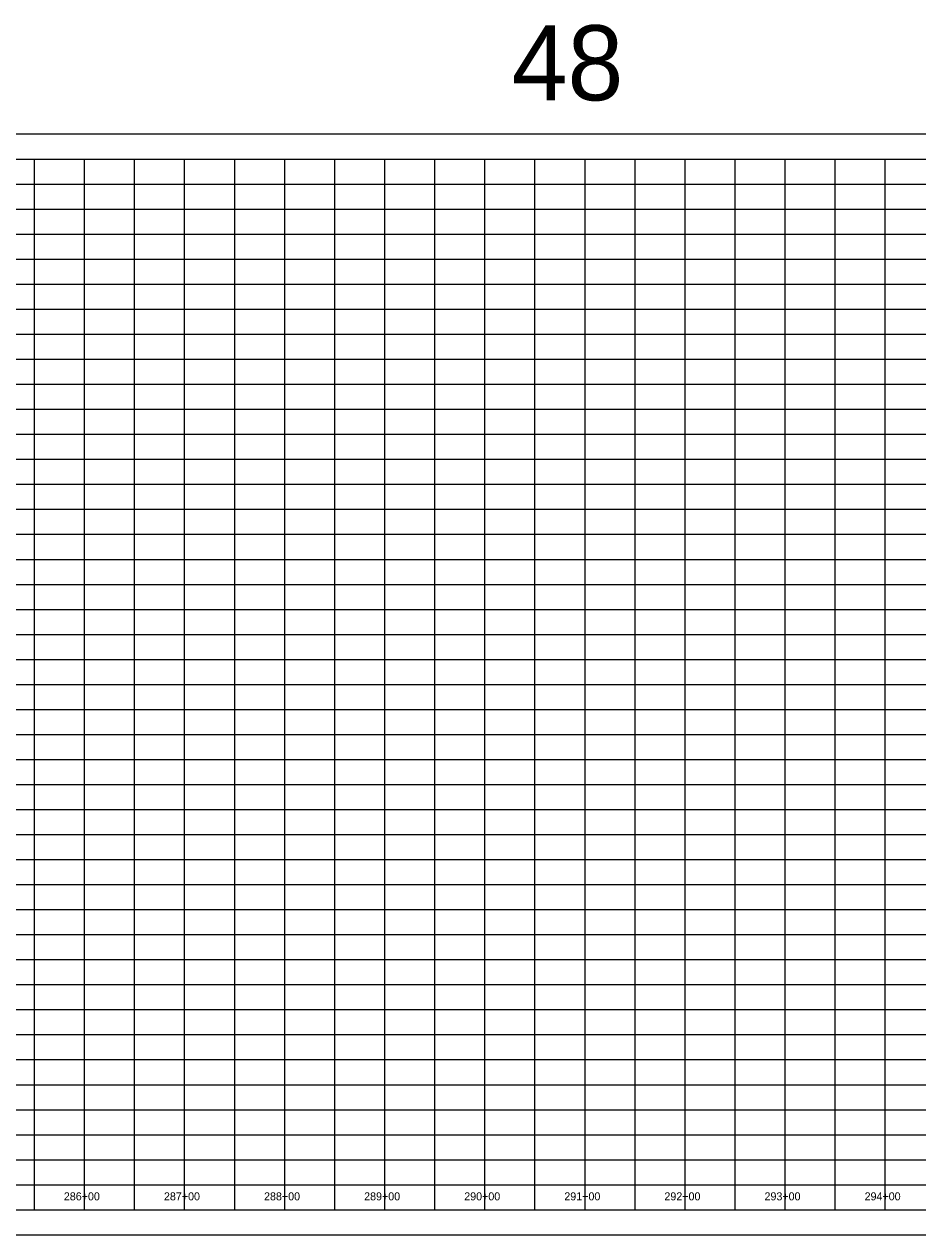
# Model space of a CAD drawing. Extents: x 1873632 to 1926512, y 813126 to 836257.
# Drawn here: x 1906903 to 1907795, y 827963 to 829173 of the extents above; entities that cross this region are included whole.
import ezdxf

# ---------------------------------------------------------------- set-up
doc = ezdxf.new("R2010")
doc.units = 0
for name, color, linetype in [('RD_DDB_StaTX', 7, 'Continuous'), ('RD_PD_WallFill', 7, 'Continuous'), ('RD_SHT_IplotShp', 7, 'Continuous')]:
    doc.layers.add(name, color=color, linetype=linetype)

msp = doc.modelspace()

# ---------------------------------------------------------------- linework, layer by layer
at = {"layer": 'RD_PD_WallFill'}
for p, q in [((1905062.9, 829038.1), (1910412.9, 829038.1)), ((1906912.9, 827988.1), (1906912.9, 829038.1)), ((1906912.9, 827988.1), (1906912.9, 829038.1)), ((1906962.9, 827988.1), (1906962.9, 829038.1)), ((1906962.9, 827988.1), (1906962.9, 829038.1)), ((1907012.9, 827988.1), (1907012.9, 829038.1)), ((1907012.9, 827988.1), (1907012.9, 829038.1)), ((1907062.9, 827988.1), (1907062.9, 829038.1)), ((1907062.9, 827988.1), (1907062.9, 829038.1)), ((1907112.9, 827988.1), (1907112.9, 829038.1)), ((1907112.9, 827988.1), (1907112.9, 829038.1)), ((1907162.9, 827988.1), (1907162.9, 829038.1)), ((1907162.9, 827988.1), (1907162.9, 829038.1)), ((1907212.9, 827988.1), (1907212.9, 829038.1)), ((1907212.9, 827988.1), (1907212.9, 829038.1)), ((1907262.9, 827988.1), (1907262.9, 829038.1)), ((1907262.9, 827988.1), (1907262.9, 829038.1)), ((1907312.9, 827988.1), (1907312.9, 829038.1)), ((1907312.9, 827988.1), (1907312.9, 829038.1)), ((1907362.9, 827988.1), (1907362.9, 829038.1)), ((1907362.9, 827988.1), (1907362.9, 829038.1)), ((1907412.9, 827988.1), (1907412.9, 829038.1)), ((1907412.9, 827988.1), (1907412.9, 829038.1)), ((1907462.9, 827988.1), (1907462.9, 829038.1)), ((1907462.9, 827988.1), (1907462.9, 829038.1)), ((1907512.9, 827988.1), (1907512.9, 829038.1)), ((1907512.9, 827988.1), (1907512.9, 829038.1)), ((1907562.9, 827988.1), (1907562.9, 829038.1)), ((1907562.9, 827988.1), (1907562.9, 829038.1)), ((1907612.9, 827988.1), (1907612.9, 829038.1)), ((1907612.9, 827988.1), (1907612.9, 829038.1)), ((1907662.9, 827988.1), (1907662.9, 829038.1)), ((1907662.9, 827988.1), (1907662.9, 829038.1)), ((1907712.9, 827988.1), (1907712.9, 829038.1)), ((1907712.9, 827988.1), (1907712.9, 829038.1)), ((1907762.9, 827988.1), (1907762.9, 829038.1)), ((1907762.9, 827988.1), (1907762.9, 829038.1)), ((1905512.9, 829013.1), (1910412.9, 829013.1)), ((1905512.9, 829013.1), (1910412.9, 829013.1)), ((1905512.9, 828988.1), (1910412.9, 828988.1)), ((1905512.9, 828963.1), (1910412.9, 828963.1)), ((1905512.9, 828938.1), (1910412.9, 828938.1)), ((1905512.9, 828913.1), (1910412.9, 828913.1)), ((1905062.9, 828888.1), (1910412.9, 828888.1)), ((1905062.9, 828863.1), (1910412.9, 828863.1)), ((1905062.9, 828838.1), (1910412.9, 828838.1)), ((1905062.9, 828813.1), (1910412.9, 828813.1)), ((1905062.9, 828788.1), (1910412.9, 828788.1)), ((1905062.9, 828763.1), (1910412.9, 828763.1)), ((1905062.9, 828738.1), (1910412.9, 828738.1)), ((1905062.9, 828713.1), (1910412.9, 828713.1)), ((1905062.9, 828688.1), (1910412.9, 828688.1)), ((1905062.9, 828663.1), (1910412.9, 828663.1)), ((1905062.9, 828638.1), (1910412.9, 828638.1)), ((1905062.9, 828613.1), (1910412.9, 828613.1)), ((1905062.9, 828588.1), (1910412.9, 828588.1)), ((1905062.9, 828563.1), (1910412.9, 828563.1)), ((1905062.9, 828538.1), (1910412.9, 828538.1)), ((1905062.9, 828513.1), (1910412.9, 828513.1)), ((1905062.9, 828488.1), (1910412.9, 828488.1)), ((1905062.9, 828463.1), (1910412.9, 828463.1)), ((1905062.9, 828438.1), (1910412.9, 828438.1)), ((1905062.9, 828413.1), (1910412.9, 828413.1)), ((1905062.9, 828388.1), (1910412.9, 828388.1)), ((1905062.9, 828363.1), (1910412.9, 828363.1)), ((1905062.9, 828338.1), (1910412.9, 828338.1)), ((1905062.9, 828313.1), (1910412.9, 828313.1)), ((1905062.9, 828288.1), (1910412.9, 828288.1)), ((1905062.9, 828263.1), (1910412.9, 828263.1)), ((1905062.9, 828238.1), (1910412.9, 828238.1)), ((1905062.9, 828213.1), (1910412.9, 828213.1)), ((1905062.9, 828188.1), (1910412.9, 828188.1)), ((1905062.9, 828163.1), (1910412.9, 828163.1)), ((1905062.9, 828138.1), (1910412.9, 828138.1)), ((1905062.9, 828113.1), (1910412.9, 828113.1)), ((1905062.9, 828088.1), (1910412.9, 828088.1)), ((1905062.9, 828063.1), (1910412.9, 828063.1)), ((1905062.9, 828038.1), (1910412.9, 828038.1)), ((1905062.9, 828013.1), (1910412.9, 828013.1)), ((1905062.9, 827988.1), (1910412.9, 827988.1)), ((1905062.9, 827988.1), (1910412.9, 827988.1))]:
    msp.add_line(p, q, dxfattribs=at)
at = {"layer": 'RD_SHT_IplotShp'}
msp.add_lwpolyline([(1905037.9, 827963.1), (1910437.9, 827963.1), (1910437.9, 829063.1), (1905037.9, 829063.1)], close=True, dxfattribs=at)

# ---------------------------------------------------------------- texts
at = {"layer": 'RD_DDB_StaTX'}
for s, p in [('286+00', (1906942.2, 827997.5)), ('287+00', (1907042.2, 827997.5)), ('288+00', (1907142.2, 827997.5)), ('289+00', (1907242.2, 827997.5)), ('290+00', (1907342.2, 827997.5)), ('291+00', (1907442.2, 827997.5)), ('292+00', (1907542.2, 827997.5)), ('293+00', (1907642.2, 827997.5)), ('294+00', (1907742.2, 827997.5))]:
    msp.add_text(s, height=8, dxfattribs=at).set_placement(p)
at = {"layer": 'RD_PD_WallFill'}
msp.add_text('48', height=75, dxfattribs=at).set_placement((1907389.6, 829096.8))
msp.add_text('48', height=75, dxfattribs=at).set_placement((1907389.6, 829096.8))

doc.saveas('drawing.dxf')
